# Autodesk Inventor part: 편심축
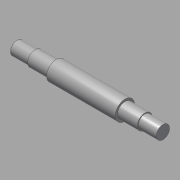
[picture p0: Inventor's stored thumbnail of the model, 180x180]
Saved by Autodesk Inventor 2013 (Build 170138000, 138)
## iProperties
Created: 2015-10
Part Number: 편심축
Document SubType Name: Modeling
Designer: mdu
Density: 1 g/cm^3
Material: 강철, 연강
Mass: 168.947 g
Surface Area: 248.524 cm^2
Volume: 168.947 cm^3
Author: mdu
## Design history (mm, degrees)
sketch "스케치1"
  geometry: L1 (-20.5, -41.331)-(-20.5, 32.669) reference; L2 (7.5, -30.031)-(7.5, 21.369) reference; L3 (135.5, -30.331)-(135.5, 21.669) reference; L4 (121.5, 21.369)-(121.5, -30.031) reference; L5 (184.5, -4.331)-(-7.5, -4.331); L6 (184.5, -4.331)-(184.5, 6.669); L7 (154.5, 8.169)-(121.5, 8.169); L8 (121.5, 8.169)-(121.5, 11.669); L9 (121.5, 11.669)-(7.5, 11.669); L10 (7.5, 11.669)-(7.5, 8.169); L11 (7.5, 8.169)-(-7.5, 8.169); L12 (-7.5, 8.169)-(-7.5, -4.331); L13 (154.5, 8.169)-(154.5, 6.669); L14 (154.5, 6.669)-(184.5, 6.669); C1 r 32.5 at (64.5, -4.331) reference; 1 further point
  constraints: 21 end point, 8 perpendicular, 5 point on line, 1 collinear
  dimensions: "d1" = 25 diameter of L11 L5; "d2" = 32 diameter of L9 L5; "d4" = 15 distance of L10.end L11.end; "d15" = 33 distance of L7.start L7.end; "d26" = 30 distance of L13.end L6.end; "d36" = 22 diameter of L14 L5
revolve "회전1" sketch "스케치1" stored, may be unused: angle "d6" = 90 deg
node "작업 평면1"
sketch "스케치2"
  geometry: C1 r 16 at (0, 0) reference; C2 r 20.75 at (0, 4)
  constraints: 1 centre point, 1 vertical alignment
  dimensions: "d34" = 4 distance of C2.centre C1.centre; "d35" = 41.5 diameter of C2
extrude "돌출1" join sketch "스케치2" stored distance "d9" = 40; taper "d10" = 0 deg
chamfer "모따기1" distance "d11" = 1; stored, may be unused: second distance "d12" = 2, angle "d13" = 45 deg
node "작업 평면2"
sketch "스케치3"
  geometry: L1 (-15, -10)-(-15, 10) reference; L2 (-15, 3)-(0, 3); L3 (0, -3)-(-15, -3); A1 r 3 centre (0, 0) between (0, -3) and (0, 3); 2 further points
  constraints: 4 end point, 2 perpendicular, 2 point on circle, 2 point on line, 2 tangent, 1 centre point, 1 horizontal alignment, 1 midpoint
  dimensions: "d16" = 18 dimension on A1 L1; "d17" = 6 distance between parallel lines of L3 L2
extrude "돌출2" cut sketch "스케치3" distance "d18" = 3.5; taper "d19" = 0 deg
node "솔리드1"
node "참조1"
node "참조2"
node "참조3"
node "참조4"
node "참조5"
other parameters: "d30" = 35
